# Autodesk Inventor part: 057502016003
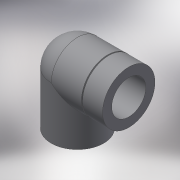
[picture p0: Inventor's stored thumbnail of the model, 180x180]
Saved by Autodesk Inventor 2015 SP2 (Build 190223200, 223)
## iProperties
Created: 2017-10
Part Number: 057502016003
Material: Generic
Description: ELBOW 90° THR-CEM REINF. R 16-3/8"
Document SubType Name: Modeling
Designer: KIM
Density: 1 g/cm^3
Appearance: Default
Author: KIM
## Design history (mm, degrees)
derived "057502.ipt"
feature "Solid1::057502.ipt"
tag "TaggingFeature1"
body "Solid1"
other parameters: "d0" = 22.5, "d1" = 23, "d3" = 23, "d4" = 23, "d6" = 90 deg, "d7" = 14.95, "d8" = 13, "d9" = 0, "d10" = 16, "d11" = 14, "d12" = 0, "d14" = 11.96, "d16" = 7.475, "d17" = 0, "d18" = 0, "d19" = 23, "d20" = 9, "d21" = 0.5, "d22" = 0.5, "d_" = 16, "G_" = 14.95, "E_" = 23, "l_" = 14, "lt_" = 13, "Z_" = 9, "H_" = 34
